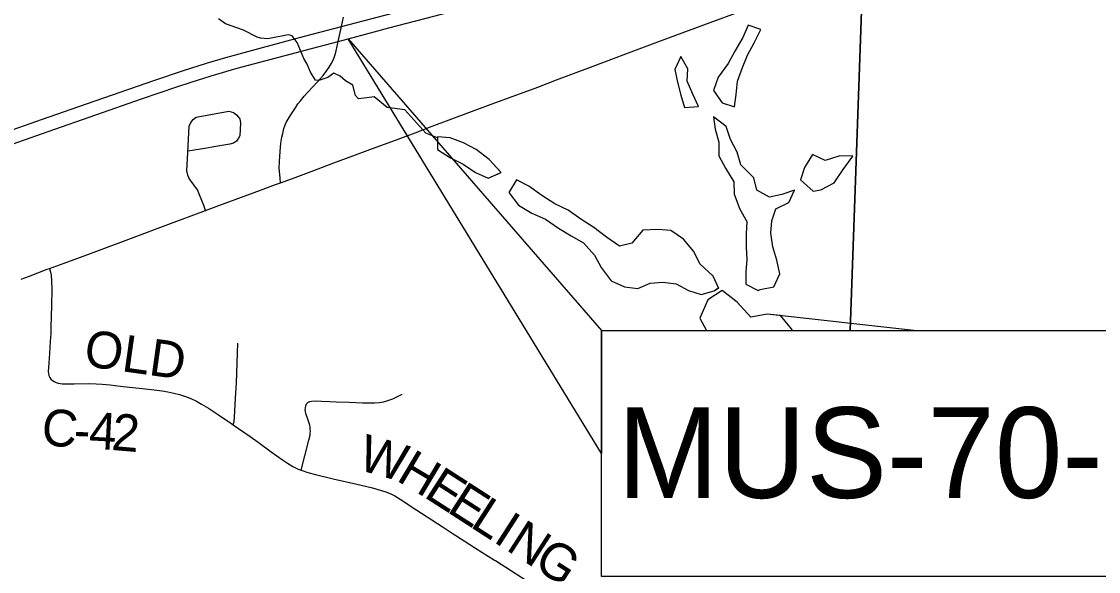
# Model space of a CAD drawing. Extents: x 0 to 34, y 0 to 22.
# Drawn here: x 4.217 to 5.879, y 15.827 to 16.675 of the extents above; entities that cross this region are included whole.
import ezdxf

# ---------------------------------------------------------------- set-up
doc = ezdxf.new("R2010")
doc.units = 0
for name, color, linetype in [('Default', 7, 'Continuous'), ('GM_X_County_Road', 7, 'Continuous'), ('GM_X_County_Road_Text', 7, 'Continuous'), ('GM_X_Interstate_Route', 7, 'Continuous'), ('GM_X_Minor_Lake', 7, 'Continuous'), ('GM_X_Minor_River', 7, 'Continuous'), ('GM_X_Rail_Line', 7, 'Continuous'), ('GM_X_Township_Road', 7, 'Continuous'), ('GM_X_US_Route', 7, 'Continuous')]:
    doc.layers.add(name, color=color, linetype=linetype)

msp = doc.modelspace()

# ---------------------------------------------------------------- linework, layer by layer
at = {"layer": 'Default'}
for points in [[(5.112, 16.0088), (4.7207, 16.6487), (5.112, 16.1987)], [(5.112, 16.1987), (6.6303, 16.1987), (6.6303, 15.8189), (5.112, 15.8189)]]:
    msp.add_lwpolyline(points, close=True, dxfattribs=at)
at = {"layer": 'GM_X_County_Road'}
for points in [[(4.6164, 16.4265), (4.6157, 16.4335), (4.6151, 16.4391), (4.6142, 16.449), (4.6147, 16.4594), (4.6157, 16.4745), (4.6171, 16.4878), (4.6184, 16.4967), (4.6198, 16.5026), (4.6217, 16.5102), (4.623, 16.5143), (4.625, 16.5193), (4.628, 16.5245), (4.6324, 16.5314), (4.6394, 16.5422), (4.6432, 16.5481), (4.647, 16.5528), (4.6531, 16.56), (4.6592, 16.5669), (4.6656, 16.5738), (4.6739, 16.5828), (4.682, 16.5922), (4.6878, 16.5996), (4.6913, 16.6048), (4.6945, 16.6099), (4.6972, 16.6148), (4.6986, 16.6184), (4.7006, 16.6243), (4.7021, 16.6303), (4.7052, 16.6446), (4.7103, 16.6674), (4.7135, 16.6819)], [(4.2597, 16.2943), (4.2614, 16.2885), (4.2624, 16.2837), (4.2631, 16.275), (4.2634, 16.262), (4.2632, 16.2373), (4.262, 16.2034), (4.2617, 16.1941), (4.2611, 16.1817), (4.26, 16.1632), (4.2581, 16.1416), (4.2579, 16.1354), (4.2581, 16.1322), (4.2589, 16.1291), (4.2602, 16.1262), (4.2621, 16.1237), (4.2645, 16.1216), (4.2672, 16.1198), (4.27, 16.1185), (4.273, 16.1175), (4.2761, 16.1169), (4.2792, 16.1165), (4.2855, 16.116), (4.2979, 16.1161), (4.3196, 16.1166), (4.332, 16.1164), (4.3413, 16.1159), (4.3536, 16.1146), (4.369, 16.1128), (4.4028, 16.1091), (4.4212, 16.107), (4.4335, 16.1055), (4.4427, 16.104), (4.4518, 16.102), (4.4607, 16.0996), (4.4696, 16.0968), (4.4782, 16.0934), (4.4865, 16.0895), (4.4946, 16.085), (4.5052, 16.0785), (4.5206, 16.0682), (4.5412, 16.0544), (4.5433, 16.053)], [(4.5433, 16.053), (4.5693, 16.0351), (4.5819, 16.0261), (4.6019, 16.0114), (4.6196, 15.9988), (4.6274, 15.9937), (4.6354, 15.9889), (4.6438, 15.9847), (4.648, 15.983)], [(4.648, 15.983), (4.6496, 15.9824), (4.6585, 15.9796), (4.6705, 15.9764), (4.6976, 15.9698), (4.734, 15.9614), (4.7581, 15.9557), (4.7701, 15.9524), (4.7789, 15.9495), (4.7875, 15.946), (4.7929, 15.9432), (4.8009, 15.9384), (4.8268, 15.9214), (4.8659, 15.8961), (4.8813, 15.8857), (4.8996, 15.874), (4.9174, 15.8626), (4.9465, 15.8444), (4.9482, 15.8434)], [(4.9482, 15.8434), (4.9887, 15.8174), (5.0038, 15.808), (5.019, 15.7979), (5.0432, 15.782), (5.0691, 15.765), (5.0933, 15.7496), (5.1112, 15.7388), (5.1271, 15.7288), (5.1365, 15.7241), (5.1416, 15.7224), (5.1447, 15.7214)]]:
    msp.add_lwpolyline(points, dxfattribs=at)
at = {"layer": 'GM_X_Interstate_Route'}
for points in [[(4.7609, 16.6592), (4.7838, 16.6653), (4.8529, 16.6836), (5.0932, 16.7471), (5.132, 16.758), (5.1647, 16.7679), (5.2061, 16.7812), (5.2414, 16.7931), (5.2823, 16.8079), (5.3288, 16.8255), (5.3663, 16.8405), (5.4006, 16.855), (5.4545, 16.879), (5.5249, 16.9113), (5.6013, 16.9464), (5.9542, 17.1082), (6.0643, 17.1589), (6.1173, 17.1828)], [(4.1848, 16.502), (4.2493, 16.5247), (4.3168, 16.5482), (4.4224, 16.585), (4.4665, 16.5999), (4.502, 16.6112), (4.5318, 16.6199), (4.5827, 16.6339), (4.6458, 16.6504), (4.7103, 16.6674), (4.9132, 16.7211)], [(4.6545, 16.6311), (4.7052, 16.6446), (4.7207, 16.6487), (4.7609, 16.6592)], [(4.1847, 16.4799), (4.258, 16.5055), (4.3313, 16.5313), (4.4016, 16.556), (4.4563, 16.5745), (4.4784, 16.5818), (4.5094, 16.5913), (4.5496, 16.6032), (4.6487, 16.6296), (4.6545, 16.6311)]]:
    msp.add_lwpolyline(points, dxfattribs=at)
at = {"layer": 'GM_X_Minor_Lake'}
for points in [[(5.3381, 16.6695), (5.3298, 16.6505), (5.3177, 16.6297), (5.3071, 16.6107), (5.2919, 16.5894), (5.2847, 16.5689), (5.298, 16.55), (5.3169, 16.5435)], [(5.3169, 16.5435), (5.3195, 16.5629), (5.3218, 16.5834), (5.3294, 16.6042), (5.3373, 16.6232), (5.3472, 16.6422), (5.3578, 16.6631), (5.3381, 16.6695), (5.3298, 16.6505), (5.3177, 16.6297), (5.3071, 16.6107), (5.2919, 16.5894), (5.2847, 16.5689), (5.298, 16.55), (5.3169, 16.5435)], [(5.3169, 16.5435), (5.3195, 16.5629), (5.3218, 16.5834), (5.3294, 16.6042), (5.3373, 16.6232), (5.3472, 16.6422), (5.3578, 16.6631), (5.3381, 16.6695)], [(5.234, 16.6213), (5.225, 16.6012), (5.2291, 16.5818), (5.2344, 16.5617), (5.2401, 16.5428), (5.2613, 16.5443)], [(5.2613, 16.5443), (5.2526, 16.5632), (5.2439, 16.5834), (5.245, 16.6023), (5.234, 16.6213), (5.225, 16.6012), (5.2291, 16.5818), (5.2344, 16.5617), (5.2401, 16.5428), (5.2613, 16.5443)], [(5.2613, 16.5443), (5.2526, 16.5632), (5.2439, 16.5834), (5.245, 16.6023), (5.234, 16.6213)], [(5.3108, 16.493), (5.3044, 16.5132), (5.2844, 16.5283), (5.287, 16.5094), (5.2927, 16.4889), (5.2927, 16.468), (5.3029, 16.449), (5.3161, 16.4278), (5.3165, 16.4088), (5.3252, 16.386), (5.3358, 16.3667), (5.3351, 16.3477), (5.3351, 16.3272), (5.3358, 16.3083), (5.3343, 16.2893), (5.3343, 16.2699), (5.3536, 16.2604), (5.3566, 16.262)], [(5.3566, 16.262), (5.3778, 16.2658), (5.3869, 16.2859), (5.3824, 16.3071), (5.3763, 16.3276), (5.3733, 16.3485), (5.3748, 16.3675), (5.3808, 16.3864), (5.4009, 16.3959), (5.4096, 16.4149), (5.3903, 16.4084), (5.371, 16.4043), (5.3517, 16.4149), (5.3468, 16.4342), (5.3267, 16.4543), (5.3211, 16.4737), (5.3108, 16.493), (5.3044, 16.5132), (5.2844, 16.5283), (5.287, 16.5094), (5.2927, 16.4889), (5.2927, 16.468), (5.3029, 16.449), (5.3161, 16.4278), (5.3165, 16.4088), (5.3252, 16.386), (5.3358, 16.3667), (5.3351, 16.3477), (5.3351, 16.3272), (5.3358, 16.3083), (5.3343, 16.2893), (5.3343, 16.2699), (5.3536, 16.2604), (5.3566, 16.262)], [(4.9567, 16.4424), (4.9385, 16.4623), (4.9181, 16.4778), (4.8988, 16.4881), (4.878, 16.4957), (4.8587, 16.4972), (4.8587, 16.4778), (4.8788, 16.4649), (4.8981, 16.4551), (4.9173, 16.4425), (4.9366, 16.4338)], [(4.9559, 16.4433), (4.9385, 16.4623), (4.9181, 16.4778), (4.8988, 16.4881), (4.878, 16.4957), (4.8587, 16.4972), (4.8587, 16.4778), (4.8788, 16.4649), (4.8981, 16.4551), (4.9173, 16.4425), (4.9366, 16.4338), (4.9552, 16.4418)], [(5.3566, 16.262), (5.3778, 16.2658), (5.3869, 16.2859), (5.3824, 16.3071), (5.3763, 16.3276), (5.3733, 16.3485), (5.3748, 16.3675), (5.3808, 16.3864), (5.4009, 16.3959), (5.4096, 16.4149), (5.3903, 16.4084), (5.371, 16.4043), (5.3517, 16.4149), (5.3468, 16.4342), (5.3267, 16.4543), (5.3211, 16.4737), (5.3108, 16.493)], [(5.4505, 16.4157), (5.4709, 16.4263), (5.4849, 16.4468), (5.4996, 16.4673), (5.4796, 16.468), (5.4569, 16.4608), (5.4376, 16.4699), (5.4251, 16.4502), (5.4191, 16.4308), (5.4384, 16.4134)], [(5.4384, 16.4134), (5.4505, 16.4157), (5.4709, 16.4263), (5.4849, 16.4468), (5.4996, 16.4673), (5.4796, 16.468), (5.4569, 16.4608), (5.4376, 16.4699), (5.4251, 16.4502), (5.4191, 16.4308), (5.4384, 16.4134), (5.4376, 16.4134)], [(4.9366, 16.4338), (4.9567, 16.4424)], [(5.284, 16.2824), (5.2636, 16.3014), (5.2541, 16.3204), (5.2382, 16.3397), (5.2189, 16.353), (5.1988, 16.3545), (5.1754, 16.3534), (5.1587, 16.3333), (5.1394, 16.3287), (5.1194, 16.3428), (5.0997, 16.3576), (5.0797, 16.3705), (5.0604, 16.3841), (5.0396, 16.394), (5.0195, 16.4069), (4.9998, 16.4213), (4.9805, 16.4308), (4.9688, 16.4114), (4.9839, 16.3921), (5.004, 16.3796), (5.0252, 16.3705), (5.0456, 16.3564), (5.0649, 16.3447), (5.0842, 16.3337), (5.1012, 16.3147), (5.1111, 16.2957), (5.1266, 16.2752), (5.1474, 16.2661), (5.1678, 16.2631), (5.1871, 16.2714), (5.2064, 16.2733), (5.2268, 16.2703), (5.2461, 16.26), (5.2658, 16.254), (5.2855, 16.2597), (5.2922, 16.2644)], [(5.2927, 16.2635), (5.284, 16.2824), (5.2636, 16.3014), (5.2541, 16.3204), (5.2382, 16.3397), (5.2189, 16.353), (5.1988, 16.3545), (5.1754, 16.3534), (5.1587, 16.3333), (5.1394, 16.3287), (5.1194, 16.3428), (5.0997, 16.3576), (5.0797, 16.3705), (5.0604, 16.3841), (5.0396, 16.394), (5.0195, 16.4069), (4.9998, 16.4213), (4.9805, 16.4308), (4.9688, 16.4114), (4.9839, 16.3921), (5.004, 16.3796), (5.0252, 16.3705), (5.0456, 16.3564), (5.0649, 16.3447), (5.0842, 16.3337), (5.1012, 16.3147), (5.1111, 16.2957), (5.1266, 16.2752), (5.1474, 16.2661), (5.1678, 16.2631), (5.1871, 16.2714), (5.2064, 16.2733), (5.2268, 16.2703), (5.2461, 16.26), (5.2658, 16.254), (5.2855, 16.2597), (5.2919, 16.2642)], [(5.4384, 16.4134), (5.4505, 16.4157)], [(5.2922, 16.2644), (5.284, 16.2824)], [(5.5938, 16.1987), (5.3674, 16.2239), (5.3424, 16.219), (5.3212, 16.2425), (5.2978, 16.2603), (5.2758, 16.2459), (5.2637, 16.2174), (5.274, 16.1987)], [(5.4066, 16.1987), (5.4048, 16.2011), (5.3878, 16.2216), (5.3674, 16.2239), (5.3424, 16.219), (5.3212, 16.2425), (5.2978, 16.2603), (5.2758, 16.2459), (5.2637, 16.2174), (5.274, 16.1987)]]:
    msp.add_lwpolyline(points, dxfattribs=at)
at = {"layer": 'GM_X_Minor_River'}
msp.add_lwpolyline([(4.8587, 16.496), (4.8404, 16.5032), (4.8081, 16.5391), (4.7808, 16.5427), (4.7611, 16.5593), (4.7494, 16.5577), (4.7369, 16.5561), (4.7323, 16.561), (4.7281, 16.577), (4.7167, 16.5837), (4.7087, 16.5909), (4.6985, 16.5958), (4.6894, 16.5889), (4.6755, 16.5843), (4.6702, 16.5846), (4.6625, 16.5971), (4.6576, 16.6096), (4.6522, 16.6183), (4.6423, 16.6429), (4.6346, 16.6531), (4.6282, 16.6546), (4.5968, 16.6484), (4.5855, 16.6495), (4.5806, 16.6513), (4.5593, 16.6622), (4.5317, 16.6719), (4.5207, 16.6795)], dxfattribs=at)
at = {"layer": 'GM_X_Rail_Line'}
for points in [[(5.6047, 18.8149), (5.5414, 17.2599), (5.5331, 17.1257), (5.5329, 17.1188), (5.5325, 17.1129), (5.5249, 16.9351), (5.5246, 16.9118), (5.5158, 16.7643), (5.4957, 16.1987)], [(5.4957, 16.1987), (5.5158, 16.7643), (5.5246, 16.9118), (5.5249, 16.9351), (5.5325, 17.1129), (5.5329, 17.1188), (5.5331, 17.1257), (5.5414, 17.2599), (5.6047, 18.8149)]]:
    msp.add_lwpolyline(points, dxfattribs=at)
at = {"layer": 'GM_X_Township_Road'}
for points in [[(4.5005, 16.3835), (4.498, 16.3912), (4.4881, 16.4156), (4.4753, 16.4333), (4.4732, 16.4382), (4.4717, 16.4451), (4.4733, 16.4731), (4.4755, 16.5137), (4.4781, 16.5196), (4.4817, 16.5242), (4.4863, 16.5278), (4.5367, 16.537), (4.5437, 16.535), (4.5485, 16.5314), (4.5534, 16.525), (4.5547, 16.5186), (4.5536, 16.4991), (4.5516, 16.4953), (4.5483, 16.4909), (4.5437, 16.4876), (4.5383, 16.486), (4.5134, 16.4819), (4.5026, 16.4801), (4.4736, 16.4751)], [(4.5433, 16.053), (4.5446, 16.0581), (4.5454, 16.0649), (4.5471, 16.0939), (4.5483, 16.1177), (4.55, 16.1638), (4.5503, 16.1792)], [(4.648, 15.983), (4.6539, 16.005), (4.6603, 16.0293), (4.662, 16.0372), (4.6624, 16.0402), (4.6625, 16.0433), (4.6623, 16.0464), (4.662, 16.0495), (4.6614, 16.0526), (4.6598, 16.0585), (4.6557, 16.0703), (4.655, 16.0733), (4.6546, 16.0763), (4.6547, 16.0794), (4.6553, 16.0824), (4.6567, 16.0852), (4.6587, 16.0875), (4.6614, 16.089), (4.6644, 16.0897), (4.6706, 16.0899), (4.6798, 16.0896), (4.6926, 16.0889), (4.7021, 16.0885), (4.7221, 16.0879), (4.743, 16.0871), (4.7538, 16.0868), (4.762, 16.0869), (4.769, 16.0874), (4.7753, 16.0885), (4.7806, 16.09), (4.7895, 16.0932), (4.804, 16.1003)]]:
    msp.add_lwpolyline(points, dxfattribs=at)
at = {"layer": 'GM_X_US_Route'}
for points in [[(4.6164, 16.4265), (4.6348, 16.4333), (4.6639, 16.4441), (4.6989, 16.4572), (4.728, 16.4679), (4.7543, 16.4776), (4.798, 16.4938), (4.8241, 16.5037), (4.8503, 16.5136), (4.9376, 16.5462), (4.9696, 16.5582), (5.0133, 16.5741), (5.0424, 16.5852), (5.0686, 16.5949), (5.0947, 16.6048), (5.118, 16.6135), (5.1616, 16.6298), (5.1907, 16.6407), (5.2169, 16.6504), (5.246, 16.6614), (5.2893, 16.6772), (5.3397, 16.696), (5.3789, 16.7113), (5.3798, 16.7117)], [(4.5005, 16.3835), (4.5212, 16.3912), (4.5562, 16.4041), (4.5853, 16.415), (4.6086, 16.4236), (4.6164, 16.4265)], [(4.2597, 16.2943), (4.2825, 16.3026), (4.3233, 16.3176), (4.3903, 16.3423), (4.4426, 16.362), (4.5005, 16.3835)], [(4.2162, 16.2776), (4.2272, 16.2819), (4.2562, 16.293), (4.2597, 16.2943)]]:
    msp.add_lwpolyline(points, dxfattribs=at)

# ---------------------------------------------------------------- texts
at = {"layer": 'Default'}
msp.add_text('MUS-70-15.234', height=0.14, dxfattribs=at).set_placement((5.1364, 15.9402))
at = {"layer": 'GM_X_County_Road_Text'}
for s, height, rotation, p in [('OLD', 0.05682, 352.0012, (4.3112, 16.1442)), ('C', 0.0568, 352.9413, (4.2452, 16.0233)), ('4', 0.0568, 357.0012, (4.3198, 16.0162)), ('2', 0.0568, 355.1335, (4.3543, 16.0144)), ('-', 0.0568, 357.7706, (4.2967, 16.0171)), ('W', 0.0568, 344.0269, (4.7336, 15.9846)), ('H', 0.0568, 329.2118, (4.7934, 15.968)), ('E', 0.0568, 327.2169, (4.8359, 15.9427)), ('E', 0.0568, 327.186, (4.8716, 15.9197)), ('L', 0.0568, 327.1898, (4.9073, 15.8966)), ('I', 0.0568, 327.1916, (4.943, 15.8736)), ('N', 0.0568, 327.188, (4.9627, 15.861)), ('G', 0.0568, 327.188, (5.0047, 15.8339))]:
    msp.add_text(s, height=height, rotation=rotation, dxfattribs=at).set_placement(p)

doc.saveas('drawing.dxf')
